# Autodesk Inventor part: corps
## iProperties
Shininess: 64.0
Length Units: 11269
Angle Units: 11279
Time Units: 11290
Mass Units: 11283
Length Display Precision: 3
Angle Display Precision: 2
Compacted: True
Part Number: corps
Document SubType Name: Modeling
Created: 2005-01
Material: Par défaut
Designer: David
Manufacturer: Standard
Standards Organization: Custom
Density: 0.0
Volumn: 0.0
Area: 0.0
PropertySet Name: Model Information
Control State: 0
Master: False
Checked Out: False
Author: David
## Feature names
1. Révolution1 [Revolution]
2. Congé1 [Fillet]
3. Extrusion1
4. Congé2 [Fillet]
5. Symétrie1 [Mirror]
6. Symétrie2 [Mirror]
7. Extrusion2
8. Extrusion3
9. Congé3 [Fillet]
10. Symétrie4 [Mirror]
11. Congé4 [Fillet]
12. Extrusion5
13. Congé5 [Fillet]
14. Extrusion10
15. Réseau rectangulaire1 [Rectangular Pattern]
16. Extrusion6
17. Symétrie5 [Mirror]
18. Extrusion11
19. Extrusion12
20. Symétrie7 [Mirror]
21. Révolution3 [Revolution]
22. Symétrie9 [Mirror]
23. Congé7 [Fillet]
24. Congé8 [Fillet]
25. Congé9 [Fillet]
26. Congé10 [Fillet]
27. Congé12 [Fillet]
28. Congé13 [Fillet]
29. Congé14 [Fillet]
30. Congé15 [Fillet]
31. Congé16 [Fillet]
